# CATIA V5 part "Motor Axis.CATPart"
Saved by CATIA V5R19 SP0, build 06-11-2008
Part number: Motor Axis
Source: Unknown
Bounding box of the stored display mesh (mm): x 76.344 to 82.344, y 6.705 to 12.705, z 25.425 to 46.425
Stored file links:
  D:\Lectures\Catia DMU Lecture Notes\Practice Files\Revolute Joint\Electric Fan\Result\Electric Fan Assembly with No SubAssembly\Motor Axis.CATPart
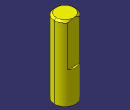
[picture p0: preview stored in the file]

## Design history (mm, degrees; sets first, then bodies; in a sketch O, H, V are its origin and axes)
Body1 "Motor Axis" (main body)
  Solid1: solid without history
